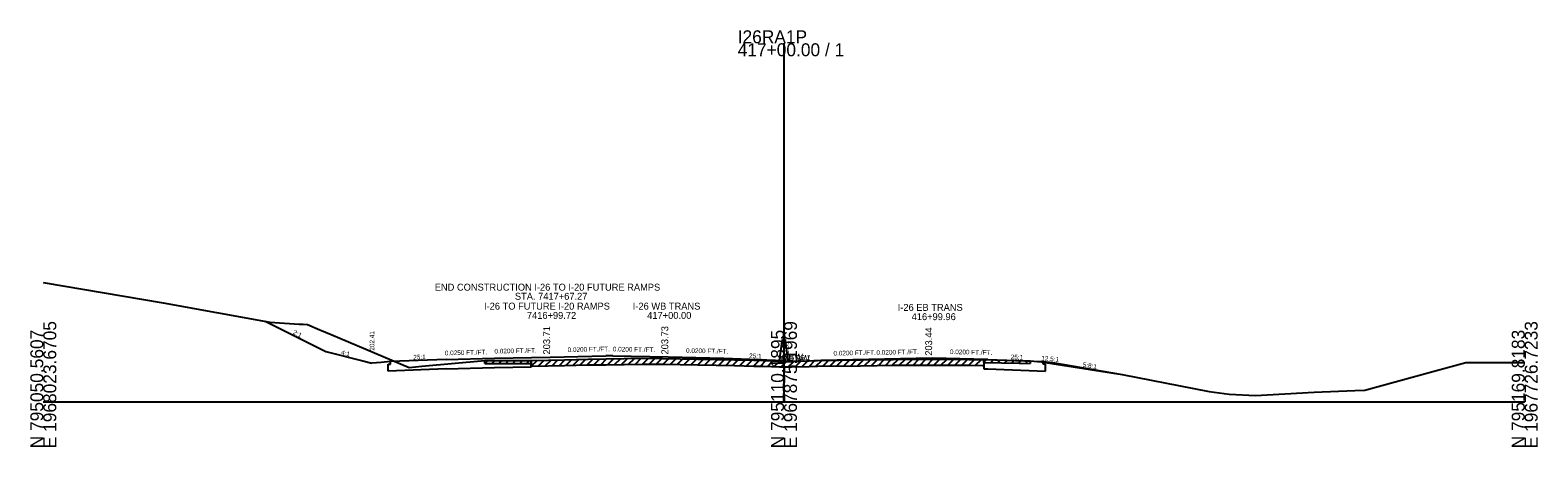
# Model space of a CAD drawing. Extents: x -44 to 4323, y -10 to 9601.
# Drawn here: x 997.2 to 1322.8, y 490.3 to 580.3 of the extents above; entities that cross this region are included whole.
import ezdxf

# ---------------------------------------------------------------- set-up
doc = ezdxf.new("R2010")
doc.units = 0
for name, color, linetype in [('1', 7, 'Continuous'), ('DateStamp', 7, 'Continuous'), ('NotForConst', 7, 'Continuous'), ('QCQA', 7, 'Continuous'), ('RD_SHT_Bndy', 7, 'Continuous'), ('RD_SHT_Iplotshp', 7, 'Continuous'), ('RD_SHT_TX', 7, 'Continuous'), ('RD_TX_Misc1', 7, 'Continuous'), ('RD_XS_ExGround', 7, 'Continuous'), ('RD_XS_MatchLine', 7, 'Continuous'), ('RD_XS_MedBWall', 7, 'Continuous'), ('RD_XS_Misc_Line', 7, 'Continuous'), ('RD_XS_Pave', 7, 'Continuous'), ('RD_XS_PaveShd', 7, 'Continuous'), ('RD_XS_TieSlope', 7, 'Continuous'), ('RD_XS_TX_Elev_PR', 7, 'Continuous'), ('RD_XS_TX_Profile', 7, 'Continuous'), ('RD_XS_TX_ShdSlope', 7, 'Continuous'), ('RD_XS_TX_Slope', 7, 'Continuous'), ('seal', 7, 'Continuous'), ('TR SN EXTRUDED PANEL SIGNS - GROUND MOUNTED', 7, 'Continuous')]:
    doc.layers.add(name, color=color, linetype=linetype)

msp = doc.modelspace()

# ---------------------------------------------------------------- linework, layer by layer
at = {"layer": 'DateStamp'}
msp.add_lwpolyline([(1000, 525.84), (1025.86, 521.45), (1048.96, 517.26), (1055.3, 516.85), (1056.14, 516.79), (1057.05, 516.73), (1059.74, 515.59), (1062.21, 514.55), (1079, 507.49), (1081.79, 507.71), (1095.4, 508.94), (1095.8, 508.94), (1105.61, 508.97), (1112.56, 509.13), (1117.73, 509.25), (1121.57, 509.31), (1129.34, 509.45), (1133.74, 509.39), (1141.4, 509.28), (1149.34, 509.11), (1153.48, 509.02), (1155.53, 508.97), (1159, 508.85), (1160, 508.85), (1160.7, 508.84), (1161.64, 508.83), (1165.45, 508.93), (1167.21, 508.97), (1176.54, 509.1), (1180.1, 509.15), (1183.55, 509.18), (1191.82, 509.24), (1199.95, 509.18), (1202.88, 509.17), (1210.82, 508.98), (1213.15, 508.93), (1215.54, 508.65), (1233.05, 505.94), (1251.81, 502.26), (1256.14, 501.72), (1261.87, 501.39), (1274.55, 502.09), (1283.33, 502.49), (1285.47, 502.53), (1299.35, 506.36), (1307.3, 508.51), (1311.02, 508.52), (1315.28, 508.56), (1320, 508.57)], dxfattribs=at)
at = {"layer": 'NotForConst'}
for p, q in [((1095.4, 508.32), (1096.02, 508.94)), ((1096.9, 508.32), (1097.52, 508.95)), ((1098.4, 508.32), (1099.02, 508.95)), ((1099.9, 508.33), (1100.52, 508.96)), ((1101.4, 508.33), (1102.02, 508.96)), ((1102.9, 508.34), (1103.52, 508.96)), ((1104.4, 508.34), (1105.02, 508.97)), ((1105.4, 507.72), (1106.67, 508.99)), ((1106.9, 507.75), (1108.18, 509.03)), ((1108.4, 507.78), (1109.68, 509.06)), ((1109.9, 507.82), (1111.18, 509.1)), ((1111.4, 507.85), (1112.68, 509.13)), ((1112.9, 507.89), (1114.18, 509.17)), ((1114.4, 507.92), (1115.68, 509.2)), ((1115.9, 507.96), (1117.18, 509.23)), ((1117.4, 507.99), (1118.67, 509.26)), ((1118.9, 508.02), (1120.17, 509.29)), ((1120.4, 508.04), (1121.67, 509.31)), ((1121.9, 508.06), (1123.17, 509.34)), ((1123.4, 508.09), (1124.67, 509.36)), ((1124.9, 508.12), (1126.17, 509.39)), ((1126.4, 508.15), (1127.67, 509.42)), ((1127.9, 508.17), (1129.17, 509.45)), ((1129.4, 508.2), (1130.63, 509.43)), ((1130.9, 508.18), (1132.13, 509.41)), ((1132.4, 508.16), (1133.63, 509.39)), ((1133.9, 508.14), (1135.13, 509.37)), ((1135.4, 508.12), (1136.63, 509.35)), ((1136.9, 508.09), (1138.13, 509.33)), ((1138.4, 508.07), (1139.63, 509.3)), ((1139.9, 508.05), (1141.13, 509.28)), ((1141.4, 508.03), (1142.62, 509.25)), ((1142.9, 508), (1144.12, 509.22)), ((1144.4, 507.97), (1145.62, 509.19)), ((1145.9, 507.93), (1147.12, 509.16)), ((1147.4, 507.9), (1148.62, 509.12)), ((1148.9, 507.87), (1150.12, 509.09)), ((1150.4, 507.84), (1151.62, 509.06)), ((1151.9, 507.81), (1153.12, 509.03)), ((1153.4, 507.77), (1154.62, 508.99)), ((1154.9, 507.74), (1156.11, 508.95)), ((1156.4, 507.69), (1157.61, 508.9)), ((1157.9, 507.64), (1159.11, 508.85)), ((1159.4, 507.6), (1160.64, 508.84)), ((1160.9, 507.59), (1162.16, 508.84)), ((1162.4, 507.6), (1163.68, 508.88)), ((1163.9, 507.64), (1165.18, 508.92)), ((1165.4, 507.68), (1166.68, 508.96)), ((1166.9, 507.71), (1168.17, 508.98)), ((1168.4, 507.74), (1169.67, 509.01)), ((1169.9, 507.76), (1171.17, 509.03)), ((1171.4, 507.78), (1172.67, 509.05)), ((1172.9, 507.8), (1174.17, 509.07)), ((1174.4, 507.82), (1175.67, 509.09)), ((1175.9, 507.85), (1177.17, 509.11)), ((1177.4, 507.86), (1178.67, 509.13)), ((1178.9, 507.88), (1180.17, 509.15)), ((1180.4, 507.9), (1181.66, 509.16)), ((1181.9, 507.91), (1183.16, 509.17)), ((1183.4, 507.93), (1184.66, 509.19)), ((1184.9, 507.94), (1186.16, 509.2)), ((1186.4, 507.95), (1187.66, 509.21)), ((1187.9, 507.96), (1189.16, 509.22)), ((1189.4, 507.97), (1190.66, 509.23)), ((1190.9, 507.98), (1192.16, 509.23)), ((1192.4, 507.98), (1193.64, 509.22)), ((1193.9, 507.97), (1195.14, 509.21)), ((1195.4, 507.96), (1196.64, 509.21)), ((1196.9, 507.95), (1198.14, 509.2)), ((1198.4, 507.94), (1199.64, 509.19)), ((1199.9, 507.94), (1201.15, 509.18)), ((1201.4, 507.93), (1202.65, 509.17)), ((1203.15, 508.54), (1203.76, 509.15)), ((1204.65, 508.5), (1205.26, 509.11)), ((1206.15, 508.47), (1206.76, 509.08)), ((1207.65, 508.43), (1208.26, 509.04)), ((1209.15, 508.4), (1209.76, 509.01)), ((1210.65, 508.36), (1211.26, 508.97)), ((1212.15, 508.33), (1212.76, 508.94))]:
    msp.add_line(p, q, dxfattribs=at)
at = {"layer": 'QCQA'}
for p, q in [((1105.4, 508.97), (1105.61, 508.97)), ((1105.4, 508.97), (1105.4, 507.59)), ((1105.61, 508.97), (1112.56, 509.13)), ((1112.56, 509.13), (1117.73, 509.25)), ((1117.73, 509.25), (1121.57, 509.31)), ((1121.57, 509.31), (1129.34, 509.45)), ((1129.34, 509.45), (1133.74, 509.39)), ((1133.74, 509.39), (1141.4, 509.28)), ((1141.4, 509.28), (1149.34, 509.11)), ((1149.34, 509.11), (1153.48, 509.02)), ((1153.48, 509.02), (1155.53, 508.97)), ((1155.53, 508.97), (1159, 508.85)), ((1159, 508.85), (1160, 508.85)), ((1160, 508.85), (1160.7, 508.84)), ((1160.7, 508.84), (1161.64, 508.83)), ((1161.64, 508.83), (1165.45, 508.93)), ((1165.45, 508.93), (1167.21, 508.97)), ((1167.21, 508.97), (1176.54, 509.1)), ((1176.54, 509.1), (1180.1, 509.15)), ((1180.1, 509.15), (1183.55, 509.18)), ((1183.55, 509.18), (1191.82, 509.24)), ((1191.82, 509.24), (1199.95, 509.18)), ((1199.95, 509.18), (1202.88, 509.17)), ((1202.88, 509.17), (1203.15, 509.16)), ((1203.15, 509.16), (1203.15, 507.17))]:
    msp.add_line(p, q, dxfattribs=at)
at = {"layer": 'RD_SHT_Bndy'}
for p, q in [((1160, 500), (1160, 577.51)), ((1000, 500), (1160, 500)), ((1160, 500), (1320, 500))]:
    msp.add_line(p, q, dxfattribs=at)
at = {"layer": 'RD_SHT_Iplotshp'}
for p, q in [((1095.4, 508.32), (1095.4, 508.94)), ((1095.4, 508.32), (1095.8, 508.32)), ((1095.8, 508.32), (1105.4, 508.34)), ((1105.4, 507.72), (1105.4, 508.97)), ((1105.4, 508.97), (1105.4, 508.34)), ((1121.57, 508.06), (1129.34, 508.2)), ((1129.34, 508.2), (1133.74, 508.14)), ((1133.74, 508.14), (1141.4, 508.03)), ((1203.15, 509.16), (1203.15, 507.91)), ((1203.15, 508.54), (1203.15, 509.16)), ((1203.15, 508.54), (1210.82, 508.36)), ((1210.82, 508.36), (1213.15, 508.31)), ((1213.15, 508.93), (1213.15, 508.31)), ((1105.4, 507.72), (1105.61, 507.72)), ((1105.61, 507.72), (1112.56, 507.88)), ((1112.56, 507.88), (1117.73, 508)), ((1117.73, 508), (1121.57, 508.06)), ((1141.4, 508.03), (1149.34, 507.86)), ((1149.34, 507.86), (1153.48, 507.77)), ((1153.48, 507.77), (1155.53, 507.72)), ((1155.53, 507.72), (1159, 507.6)), ((1159, 507.6), (1160, 507.6)), ((1160, 507.6), (1160.7, 507.59)), ((1160.7, 507.59), (1161.64, 507.58)), ((1161.64, 507.58), (1165.45, 507.68)), ((1165.45, 507.68), (1167.21, 507.72)), ((1167.21, 507.72), (1176.54, 507.85)), ((1176.54, 507.85), (1180.1, 507.9)), ((1180.1, 507.9), (1183.55, 507.93)), ((1183.55, 507.93), (1191.82, 507.99)), ((1191.82, 507.99), (1199.95, 507.93)), ((1199.95, 507.93), (1202.88, 507.92)), ((1202.88, 507.92), (1203.15, 507.91))]:
    msp.add_line(p, q, dxfattribs=at)
at = {"layer": 'RD_TX_Misc1'}
for p in [(1069, 508.91), (1073, 508.57)]:
    msp.add_line(p, (1071, 508.41), dxfattribs=at)
at = {"layer": 'RD_XS_Misc_Line'}
for p, q in [((1074.5, 508.15), (1075, 508.17)), ((1074.5, 506.67), (1074.5, 508.15)), ((1075, 508.17), (1075, 508.73)), ((1216, 508.16), (1216, 508.72)), ((1216.5, 508.14), (1216, 508.16)), ((1216.5, 506.66), (1216.5, 508.14)), ((1087, 507.17), (1074.5, 506.67)), ((1087, 507.17), (1097.48, 507.43)), ((1097.48, 507.43), (1105.4, 507.59)), ((1203.15, 507.17), (1204, 507.16)), ((1204, 507.16), (1216.5, 506.66))]:
    msp.add_line(p, q, dxfattribs=at)
at = {"layer": 'RD_XS_Pave'}
for p, q in [((1047.92, 517.44), (1061, 510.91)), ((1061, 510.91), (1069, 508.91)), ((1218, 508.56), (1233.05, 505.94))]:
    msp.add_line(p, q, dxfattribs=at)
at = {"layer": 'RD_XS_PaveShd'}
for p, q in [((1075, 508.73), (1073, 508.57)), ((1216, 508.72), (1218, 508.56))]:
    msp.add_line(p, q, dxfattribs=at)
at = {"layer": 'RD_XS_TieSlope'}
msp.add_line((1160, 508.97), (1160, 508.63), dxfattribs=at)
at = {"layer": 'RD_XS_TX_Elev_PR'}
for p, q in [((1087, 509.21), (1075, 508.73)), ((1123, 509.97), (1121.49, 509.95)), ((1147, 509.49), (1160, 508.97)), ((1168, 508.95), (1160, 508.63)), ((1204, 509.2), (1216, 508.72))]:
    msp.add_line(p, q, dxfattribs=at)
at = {"layer": 'RD_XS_TX_ShdSlope'}
for p, q in [((1159, 508.99), (1159.67, 513.47)), ((1160.33, 513.47), (1159.67, 513.47)), ((1160.33, 513.13), (1160.33, 513.47)), ((1161, 508.65), (1160.33, 513.13))]:
    msp.add_line(p, q, dxfattribs=at)
at = {"layer": 'RD_XS_TX_Slope'}
for p, q in [((1087, 509.21), (1097.48, 509.47)), ((1097.48, 509.47), (1109.48, 509.71)), ((1109.48, 509.71), (1121.49, 509.95)), ((1123, 509.97), (1135, 509.73)), ((1135, 509.73), (1147, 509.49)), ((1192, 509.44), (1168, 508.95)), ((1204, 509.2), (1192, 509.44))]:
    msp.add_line(p, q, dxfattribs=at)

# ---------------------------------------------------------------- texts
at = {"layer": '1'}
for s, p in [('I-26 TO FUTURE I-20 RAMPS', (1095.2, 519.96)), ('I-26 WB TRANS', (1127.33, 519.96)), ('I-26 EB TRANS', (1184.56, 519.69)), ('7416+99.72', (1104.46, 517.96)), ('417+00.00', (1130.45, 517.96)), ('416+99.96', (1187.57, 517.69))]:
    msp.add_text(s, height=1.5, dxfattribs=at).set_placement(p)
at = {"layer": 'RD_SHT_Bndy'}
for s, p in [('I26RA1P', (1150, 577.51)), ('417+00.00 / 1', (1150, 574.71))]:
    msp.add_text(s, height=2.8, dxfattribs=at).set_placement(p)
for s, p in [('N 795050.5607', (1000, 490)), ('E 1968023.6705', (1002.8, 490)), ('N 795110.1895', (1160, 490)), ('E 1967875.1969', (1162.8, 490)), ('N 795169.8183', (1320, 490)), ('E 1967726.7233', (1322.8, 490))]:
    msp.add_text(s, height=2.8, rotation=90, dxfattribs=at).set_placement(p)
at = {"layer": 'RD_SHT_TX'}
msp.add_text('202.85', height=1, rotation=90, dxfattribs=at).set_placement((1161, 508.85))
at = {"layer": 'RD_XS_ExGround'}
for rotation, p in [(2.29, (1079.93, 509.17)), (357.7094, (1152.46, 509.5)), (2.2903, (1162.93, 509)), (357.7097, (1208.96, 509.25))]:
    msp.add_text('25:1', height=1, rotation=rotation, dxfattribs=at).set_placement(p)
at = {"layer": 'RD_XS_MatchLine'}
for s, p in [('END CONSTRUCTION I-26 TO I-20 FUTURE RAMPS', (1084.56, 524.06)), ('STA. 7417+67.27', (1101.87, 522.09))]:
    msp.add_text(s, height=1.5, dxfattribs=at).set_placement(p)
at = {"layer": 'RD_XS_MedBWall'}
msp.add_text('12.5:1', height=1, rotation=355.4267, dxfattribs=at).set_placement((1215.55, 509))
at = {"layer": 'RD_XS_TX_Profile'}
for s, p in [('WBW', (1159, 508.97)), ('EBW', (1161, 508.65))]:
    msp.add_text(s, height=1.5, dxfattribs=at).set_placement(p)
at = {"layer": 'seal'}
for s, p in [(' 203.71', (1109.48, 509.71)), (' 203.73', (1135, 509.71)), (' 203.44', (1192, 509.44))]:
    msp.add_text(s, height=1.5, rotation=90, dxfattribs=at).set_placement(p)
at = {"layer": 'TR SN EXTRUDED PANEL SIGNS - GROUND MOUNTED'}
for s, rotation, p in [('2:1', 333.4349, (1053.83, 514.74)), ('202.41', 90, (1071.5, 511.09)), ('0.0200 FT./FT.', 1.1498, (1097.46, 510.47)), ('0.0200 FT./FT.', 1.1448, (1113.27, 510.79)), ('0.0200 FT./FT.', 358.8542, (1123.02, 510.95)), ('0.0200 FT./FT.', 358.8542, (1138.83, 510.63)), ('0.0200 FT./FT.', 1.1503, (1179.98, 510.19)), ('0.0200 FT./FT.', 358.8594, (1195.83, 510.36)), ('4:1', 345.9638, (1064.25, 510.29)), ('0.0250 FT./FT.', 1.4321, (1086.75, 510.08)), ('0.0200 FT./FT.', 1.1503, (1170.7, 510.03)), ('5:8:1', 350.5377, (1224.47, 507.63))]:
    msp.add_text(s, height=1, rotation=rotation, dxfattribs=at).set_placement(p)

doc.saveas('drawing.dxf')
